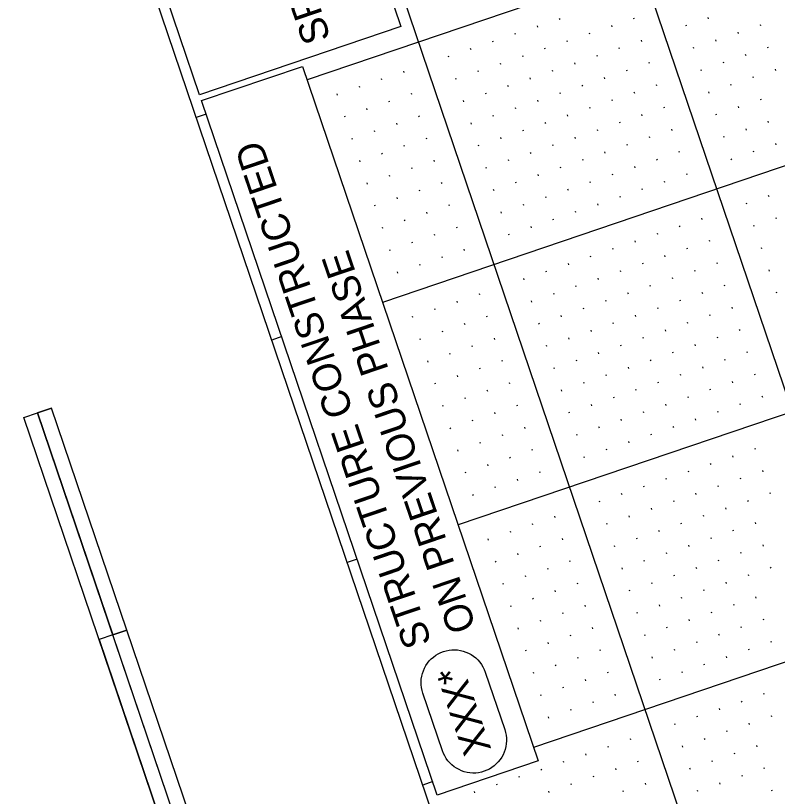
# Model space of a CAD drawing. Extents: x 2150800 to 2152547, y 141860 to 143950.
# Drawn here: x 2151773.3 to 2151935.4, y 142302.8 to 142468.9 of the extents above; entities that cross this region are included whole.
import ezdxf

# ---------------------------------------------------------------- set-up
doc = ezdxf.new("R2010")
doc.units = 0
for name, color, linetype in [('PR_Grading_Txt', 7, 'Continuous'), ('PR_Misc_Improvement', 7, 'Continuous'), ('PR_Storm_Txt_PH1B', 7, 'Continuous'), ('SHT_Profile_Grid_Major', 7, 'Continuous'), ('SHT_Profile_Grid_Minor', 7, 'Continuous'), ('SHT_Scale', 7, 'Continuous'), ('SHT_Sheet_Border', 7, 'Continuous')]:
    doc.layers.add(name, color=color, linetype=linetype)

msp = doc.modelspace()

# ---------------------------------------------------------------- linework, layer by layer
at = {"layer": 'PR_Misc_Improvement'}
for points in [[(2151812.44, 142452.11), (2151783.11, 142538.56), (2151825.94, 142553.09), (2151855.27, 142466.63)], [(2151863, 142303.07), (2151812.86, 142450.86), (2151834.34, 142458.14), (2151884.47, 142310.35)]]:
    msp.add_lwpolyline(points, close=True, dxfattribs=at)
at = {"layer": 'PR_Storm_Txt_PH1B'}
for points in [[(2151859.94, 142324.75), (2151859.77, 142325.34), (2151859.65, 142325.94), (2151859.59, 142326.54), (2151859.57, 142327.15), (2151859.61, 142327.76), (2151859.71, 142328.37), (2151859.85, 142328.96), (2151860.05, 142329.54), (2151860.29, 142330.1), (2151860.59, 142330.63), (2151860.93, 142331.14), (2151861.31, 142331.62), (2151861.73, 142332.06), (2151862.19, 142332.46), (2151862.68, 142332.82), (2151863.21, 142333.14), (2151863.75, 142333.41), (2151864.32, 142333.63), (2151864.32, 142333.63), (2151864.91, 142333.8), (2151865.51, 142333.92), (2151866.12, 142333.99), (2151866.73, 142334), (2151867.34, 142333.96), (2151867.94, 142333.87), (2151868.53, 142333.72), (2151869.11, 142333.52), (2151869.67, 142333.28), (2151870.2, 142332.98), (2151870.71, 142332.64), (2151871.19, 142332.26), (2151871.63, 142331.84), (2151872.03, 142331.38), (2151872.39, 142330.89), (2151872.71, 142330.37), (2151872.98, 142329.82), (2151873.2, 142329.25)], [(2151873.2, 142329.25), (2151877.35, 142317.01)], [(2151864.09, 142312.52), (2151859.94, 142324.75)], [(2151877.35, 142317.01), (2151877.52, 142316.43), (2151877.64, 142315.83), (2151877.71, 142315.22), (2151877.72, 142314.61), (2151877.68, 142314), (2151877.59, 142313.4), (2151877.44, 142312.8), (2151877.25, 142312.23), (2151877, 142311.67), (2151876.71, 142311.13), (2151876.37, 142310.62), (2151875.98, 142310.15), (2151875.56, 142309.71), (2151875.1, 142309.3), (2151874.61, 142308.94), (2151874.09, 142308.63), (2151873.54, 142308.36), (2151872.97, 142308.14), (2151872.97, 142308.14), (2151872.39, 142307.96), (2151871.79, 142307.85), (2151871.18, 142307.78), (2151870.57, 142307.77), (2151869.96, 142307.81), (2151869.36, 142307.9), (2151868.76, 142308.04), (2151868.18, 142308.24), (2151867.63, 142308.49), (2151867.09, 142308.78), (2151866.58, 142309.12), (2151866.11, 142309.5), (2151865.67, 142309.92), (2151865.26, 142310.38), (2151864.9, 142310.88), (2151864.59, 142311.4), (2151864.32, 142311.95), (2151864.09, 142312.52)]]:
    msp.add_lwpolyline(points, dxfattribs=at)
at = {"layer": 'SHT_Profile_Grid_Major'}
for p, q in [((2151982.71, 142254.48), (2151476.72, 143745.99)), ((2151935.36, 142238.42), (2151429.37, 143729.93)), ((2152285.21, 142607.9), (2151835.31, 142455.27)), ((2152301.27, 142560.55), (2151851.37, 142407.92)), ((2152317.33, 142513.2), (2151867.44, 142360.57)), ((2152333.4, 142465.85), (2151883.5, 142313.22)), ((2151813.84, 142447.99), (2151811.71, 142447.26)), ((2151829.9, 142400.64), (2151827.78, 142399.91)), ((2151845.97, 142353.29), (2151843.84, 142352.56)), ((2151862.03, 142305.94), (2151859.9, 142305.22))]:
    msp.add_line(p, q, dxfattribs=at)
at = {"layer": 'SHT_Profile_Grid_Minor'}
for p, q in [((2151920.74, 142468.28), (2151920.66, 142468.52)), ((2151889.12, 142468.11), (2151889.04, 142468.35)), ((2151900.2, 142466.59), (2151900.12, 142466.83)), ((2151904.93, 142468.2), (2151904.85, 142468.43)), ((2151916.01, 142466.67), (2151915.93, 142466.91)), ((2151931.82, 142466.76), (2151931.74, 142466.99)), ((2151879.65, 142464.9), (2151879.57, 142465.14)), ((2151884.38, 142466.51), (2151884.3, 142466.74)), ((2151895.46, 142464.98), (2151895.38, 142465.22)), ((2151927.08, 142465.15), (2151927, 142465.39)), ((2151874.91, 142463.29), (2151874.83, 142463.53)), ((2151890.73, 142463.38), (2151890.65, 142463.61)), ((2151906.54, 142463.46), (2151906.46, 142463.7)), ((2151922.35, 142463.54), (2151922.27, 142463.78)), ((2151870.18, 142461.69), (2151870.1, 142461.92)), ((2151885.99, 142461.77), (2151885.91, 142462.01)), ((2151901.8, 142461.85), (2151901.72, 142462.09)), ((2151917.61, 142461.94), (2151917.53, 142462.18)), ((2151933.42, 142462.02), (2151933.34, 142462.26)), ((2151865.44, 142460.08), (2151865.36, 142460.32)), ((2151881.26, 142460.16), (2151881.18, 142460.4)), ((2151897.07, 142460.25), (2151896.99, 142460.48)), ((2151928.69, 142460.42), (2151928.61, 142460.65)), ((2151876.52, 142458.56), (2151876.44, 142458.79)), ((2151892.33, 142458.64), (2151892.25, 142458.88)), ((2151908.14, 142458.73), (2151908.06, 142458.96)), ((2151923.95, 142458.81), (2151923.87, 142459.05)), ((2151855.97, 142456.87), (2151855.89, 142457.1)), ((2151871.79, 142456.95), (2151871.71, 142457.19)), ((2151887.6, 142457.04), (2151887.52, 142457.27)), ((2151903.41, 142457.12), (2151903.33, 142457.36)), ((2151919.22, 142457.2), (2151919.14, 142457.44)), ((2151935.03, 142457.29), (2151934.95, 142457.52)), ((2151851.24, 142455.26), (2151851.16, 142455.5)), ((2151867.05, 142455.35), (2151866.97, 142455.58)), ((2151882.86, 142455.43), (2151882.78, 142455.67)), ((2151898.67, 142455.51), (2151898.59, 142455.75)), ((2151930.3, 142455.68), (2151930.22, 142455.92)), ((2151846.5, 142453.65), (2151846.42, 142453.89)), ((2151878.13, 142453.82), (2151878.05, 142454.06)), ((2151893.94, 142453.91), (2151893.86, 142454.14)), ((2151909.75, 142453.99), (2151909.67, 142454.23)), ((2151925.56, 142454.07), (2151925.48, 142454.31)), ((2151841.77, 142452.05), (2151841.69, 142452.29)), ((2151857.58, 142452.13), (2151857.5, 142452.37)), ((2151873.39, 142452.22), (2151873.31, 142452.45)), ((2151889.2, 142452.3), (2151889.12, 142452.54)), ((2151905.01, 142452.38), (2151904.93, 142452.62)), ((2151920.83, 142452.47), (2151920.75, 142452.71)), ((2151852.85, 142450.53), (2151852.77, 142450.76)), ((2151868.66, 142450.61), (2151868.58, 142450.85)), ((2151884.47, 142450.69), (2151884.39, 142450.93)), ((2151900.28, 142450.78), (2151900.2, 142451.01)), ((2151931.9, 142450.95), (2151931.82, 142451.18)), ((2151848.11, 142448.92), (2151848.03, 142449.16)), ((2151879.73, 142449.09), (2151879.65, 142449.32)), ((2151895.54, 142449.17), (2151895.46, 142449.41)), ((2151911.36, 142449.26), (2151911.28, 142449.49)), ((2151927.17, 142449.34), (2151927.09, 142449.58)), ((2151843.38, 142447.31), (2151843.3, 142447.55)), ((2151859.19, 142447.4), (2151859.11, 142447.63)), ((2151875, 142447.48), (2151874.92, 142447.72)), ((2151890.81, 142447.57), (2151890.73, 142447.8)), ((2151906.62, 142447.65), (2151906.54, 142447.89)), ((2151922.43, 142447.73), (2151922.35, 142447.97)), ((2151854.45, 142445.79), (2151854.37, 142446.03)), ((2151870.26, 142445.88), (2151870.18, 142446.11)), ((2151886.07, 142445.96), (2151885.99, 142446.2)), ((2151901.89, 142446.04), (2151901.81, 142446.28)), ((2151933.51, 142446.21), (2151933.43, 142446.45)), ((2151849.72, 142444.18), (2151849.64, 142444.42)), ((2151881.34, 142444.35), (2151881.26, 142444.59)), ((2151897.15, 142444.44), (2151897.07, 142444.67)), ((2151912.96, 142444.52), (2151912.88, 142444.76)), ((2151928.77, 142444.6), (2151928.69, 142444.84)), ((2151844.98, 142442.58), (2151844.9, 142442.82)), ((2151860.79, 142442.66), (2151860.71, 142442.9)), ((2151876.6, 142442.75), (2151876.52, 142442.98)), ((2151892.42, 142442.83), (2151892.34, 142443.07)), ((2151908.23, 142442.91), (2151908.15, 142443.15)), ((2151924.04, 142443), (2151923.96, 142443.24)), ((2151856.06, 142441.06), (2151855.98, 142441.29)), ((2151871.87, 142441.14), (2151871.79, 142441.38)), ((2151887.68, 142441.22), (2151887.6, 142441.46)), ((2151903.49, 142441.31), (2151903.41, 142441.55)), ((2151935.11, 142441.48), (2151935.03, 142441.71)), ((2151851.32, 142439.45), (2151851.24, 142439.69)), ((2151882.95, 142439.62), (2151882.87, 142439.85)), ((2151898.76, 142439.7), (2151898.68, 142439.94)), ((2151914.57, 142439.79), (2151914.49, 142440.02)), ((2151930.38, 142439.87), (2151930.3, 142440.11)), ((2151846.59, 142437.84), (2151846.51, 142438.08)), ((2151862.4, 142437.93), (2151862.32, 142438.16)), ((2151878.21, 142438.01), (2151878.13, 142438.25)), ((2151894.02, 142438.1), (2151893.94, 142438.33)), ((2151909.83, 142438.18), (2151909.75, 142438.42)), ((2151925.64, 142438.26), (2151925.56, 142438.5)), ((2151857.66, 142436.32), (2151857.58, 142436.56)), ((2151873.48, 142436.41), (2151873.4, 142436.64)), ((2151889.29, 142436.49), (2151889.21, 142436.73)), ((2151905.1, 142436.57), (2151905.02, 142436.81)), ((2151916.17, 142435.05), (2151916.09, 142435.29)), ((2151852.93, 142434.72), (2151852.85, 142434.95)), ((2151884.55, 142434.88), (2151884.47, 142435.12)), ((2151895.63, 142433.36), (2151895.55, 142433.6)), ((2151900.36, 142434.97), (2151900.28, 142435.2)), ((2151911.44, 142433.44), (2151911.36, 142433.68)), ((2151848.19, 142433.11), (2151848.11, 142433.35)), ((2151864.01, 142433.19), (2151863.93, 142433.43)), ((2151875.08, 142431.67), (2151875, 142431.91)), ((2151879.82, 142433.28), (2151879.74, 142433.51)), ((2151890.89, 142431.75), (2151890.81, 142431.99)), ((2151906.7, 142431.84), (2151906.62, 142432.08)), ((2151859.27, 142431.59), (2151859.19, 142431.82)), ((2151886.16, 142430.15), (2151886.08, 142430.38)), ((2151901.97, 142430.23), (2151901.89, 142430.47)), ((2151933.59, 142430.4), (2151933.51, 142430.64)), ((2151849.8, 142428.37), (2151849.72, 142428.61)), ((2151854.54, 142429.98), (2151854.46, 142430.22)), ((2151865.61, 142428.46), (2151865.53, 142428.69)), ((2151881.42, 142428.54), (2151881.34, 142428.78)), ((2151897.23, 142428.63), (2151897.15, 142428.86)), ((2151928.86, 142428.79), (2151928.78, 142429.03)), ((2151860.88, 142426.85), (2151860.8, 142427.09)), ((2151876.69, 142426.94), (2151876.61, 142427.17)), ((2151892.5, 142427.02), (2151892.42, 142427.26)), ((2151856.14, 142425.25), (2151856.06, 142425.48)), ((2151887.76, 142425.41), (2151887.68, 142425.65)), ((2151919.39, 142425.58), (2151919.31, 142425.82)), ((2151935.2, 142425.67), (2151935.12, 142425.9)), ((2151851.41, 142423.64), (2151851.33, 142423.88)), ((2151867.22, 142423.72), (2151867.14, 142423.96)), ((2151883.03, 142423.81), (2151882.95, 142424.04)), ((2151914.65, 142423.97), (2151914.57, 142424.21)), ((2151930.46, 142424.06), (2151930.38, 142424.3)), ((2151862.48, 142422.12), (2151862.4, 142422.35)), ((2151878.3, 142422.2), (2151878.21, 142422.44)), ((2151909.92, 142422.37), (2151909.84, 142422.61)), ((2151857.75, 142420.51), (2151857.67, 142420.75)), ((2151905.18, 142420.76), (2151905.1, 142421)), ((2151920.99, 142420.85), (2151920.91, 142421.08)), ((2151853.01, 142418.9), (2151852.93, 142419.14)), ((2151868.83, 142418.99), (2151868.74, 142419.22)), ((2151900.45, 142419.16), (2151900.37, 142419.39)), ((2151916.26, 142419.24), (2151916.18, 142419.48)), ((2151932.07, 142419.32), (2151931.99, 142419.56)), ((2151864.09, 142417.38), (2151864.01, 142417.62)), ((2151895.71, 142417.55), (2151895.63, 142417.79)), ((2151911.52, 142417.63), (2151911.44, 142417.87)), ((2151859.36, 142415.78), (2151859.27, 142416.01)), ((2151890.98, 142415.94), (2151890.9, 142416.18)), ((2151906.79, 142416.03), (2151906.71, 142416.26)), ((2151922.6, 142416.11), (2151922.52, 142416.35)), ((2151854.62, 142414.17), (2151854.54, 142414.41)), ((2151886.24, 142414.34), (2151886.16, 142414.57)), ((2151902.05, 142414.42), (2151901.97, 142414.66)), ((2151917.86, 142414.5), (2151917.78, 142414.74)), ((2151933.68, 142414.59), (2151933.6, 142414.83)), ((2151881.51, 142412.73), (2151881.43, 142412.97)), ((2151897.32, 142412.81), (2151897.24, 142413.05)), ((2151913.13, 142412.9), (2151913.05, 142413.14)), ((2151892.58, 142411.21), (2151892.5, 142411.45)), ((2151908.4, 142411.29), (2151908.31, 142411.53)), ((2151924.21, 142411.38), (2151924.13, 142411.61)), ((2151872.04, 142409.52), (2151871.96, 142409.75)), ((2151887.85, 142409.6), (2151887.77, 142409.84)), ((2151903.66, 142409.69), (2151903.58, 142409.92)), ((2151919.47, 142409.77), (2151919.39, 142410.01)), ((2151935.28, 142409.85), (2151935.2, 142410.09)), ((2151867.3, 142407.91), (2151867.22, 142408.15)), ((2151883.11, 142408), (2151883.03, 142408.23)), ((2151898.93, 142408.08), (2151898.84, 142408.32)), ((2151914.74, 142408.16), (2151914.66, 142408.4)), ((2151862.57, 142406.31), (2151862.49, 142406.54)), ((2151894.19, 142406.47), (2151894.11, 142406.71)), ((2151910, 142406.56), (2151909.92, 142406.79)), ((2151925.81, 142406.64), (2151925.73, 142406.88)), ((2151857.83, 142404.7), (2151857.75, 142404.94)), ((2151873.64, 142404.78), (2151873.56, 142405.02)), ((2151889.46, 142404.87), (2151889.37, 142405.1)), ((2151905.27, 142404.95), (2151905.19, 142405.19)), ((2151916.34, 142403.43), (2151916.26, 142403.67)), ((2151921.08, 142405.04), (2151921, 142405.27)), ((2151868.91, 142403.18), (2151868.83, 142403.41)), ((2151884.72, 142403.26), (2151884.64, 142403.5)), ((2151900.53, 142403.34), (2151900.45, 142403.58)), ((2151911.61, 142401.82), (2151911.53, 142402.06)), ((2151927.42, 142401.91), (2151927.34, 142402.14)), ((2151864.17, 142401.57), (2151864.09, 142401.81)), ((2151891.06, 142400.13), (2151890.98, 142400.37)), ((2151895.8, 142401.74), (2151895.72, 142401.98)), ((2151906.87, 142400.22), (2151906.79, 142400.45)), ((2151922.68, 142400.3), (2151922.6, 142400.54)), ((2151859.44, 142399.96), (2151859.36, 142400.2)), ((2151870.52, 142398.44), (2151870.44, 142398.68)), ((2151875.25, 142400.05), (2151875.17, 142400.28)), ((2151886.33, 142398.53), (2151886.25, 142398.76)), ((2151902.14, 142398.61), (2151902.06, 142398.85)), ((2151917.95, 142398.69), (2151917.87, 142398.93)), ((2151865.78, 142396.84), (2151865.7, 142397.07)), ((2151897.4, 142397), (2151897.32, 142397.24)), ((2151913.21, 142397.09), (2151913.13, 142397.32)), ((2151929.03, 142397.17), (2151928.94, 142397.41)), ((2151861.05, 142395.23), (2151860.97, 142395.47)), ((2151876.86, 142395.31), (2151876.78, 142395.55)), ((2151892.67, 142395.4), (2151892.59, 142395.63)), ((2151908.48, 142395.48), (2151908.4, 142395.72)), ((2151924.29, 142395.57), (2151924.21, 142395.8)), ((2151872.12, 142393.71), (2151872.04, 142393.94)), ((2151887.93, 142393.79), (2151887.85, 142394.03)), ((2151903.74, 142393.87), (2151903.66, 142394.11)), ((2151919.56, 142393.96), (2151919.47, 142394.2)), ((2151867.39, 142392.1), (2151867.31, 142392.34)), ((2151899.01, 142392.27), (2151898.93, 142392.51)), ((2151914.82, 142392.35), (2151914.74, 142392.59)), ((2151930.63, 142392.44), (2151930.55, 142392.67)), ((2151862.65, 142390.49), (2151862.57, 142390.73)), ((2151878.46, 142390.58), (2151878.38, 142390.81)), ((2151894.27, 142390.66), (2151894.19, 142390.9)), ((2151910.09, 142390.75), (2151910.01, 142390.98)), ((2151925.9, 142390.83), (2151925.82, 142391.07)), ((2151873.73, 142388.97), (2151873.65, 142389.21)), ((2151889.54, 142389.06), (2151889.46, 142389.29)), ((2151905.35, 142389.14), (2151905.27, 142389.38)), ((2151921.16, 142389.22), (2151921.08, 142389.46)), ((2151868.99, 142387.37), (2151868.91, 142387.6)), ((2151900.62, 142387.53), (2151900.54, 142387.77)), ((2151916.43, 142387.62), (2151916.35, 142387.85)), ((2151932.24, 142387.7), (2151932.16, 142387.94)), ((2151864.26, 142385.76), (2151864.18, 142386)), ((2151880.07, 142385.84), (2151879.99, 142386.08)), ((2151895.88, 142385.93), (2151895.8, 142386.16)), ((2151911.69, 142386.01), (2151911.61, 142386.25)), ((2151927.5, 142386.1), (2151927.42, 142386.33)), ((2151875.33, 142384.24), (2151875.25, 142384.47)), ((2151891.15, 142384.32), (2151891.07, 142384.56)), ((2151906.96, 142384.4), (2151906.88, 142384.64)), ((2151922.77, 142384.49), (2151922.69, 142384.73)), ((2151870.6, 142382.63), (2151870.52, 142382.87)), ((2151902.22, 142382.8), (2151902.14, 142383.04)), ((2151918.03, 142382.88), (2151917.95, 142383.12)), ((2151865.86, 142381.02), (2151865.78, 142381.26)), ((2151881.68, 142381.11), (2151881.6, 142381.35)), ((2151897.49, 142381.19), (2151897.41, 142381.43)), ((2151913.3, 142381.28), (2151913.22, 142381.51)), ((2151876.94, 142379.5), (2151876.86, 142379.74)), ((2151892.75, 142379.59), (2151892.67, 142379.82)), ((2151908.56, 142379.67), (2151908.48, 142379.91)), ((2151872.21, 142377.9), (2151872.13, 142378.13)), ((2151903.83, 142378.06), (2151903.75, 142378.3)), ((2151867.47, 142376.29), (2151867.39, 142376.53)), ((2151883.28, 142376.37), (2151883.2, 142376.61)), ((2151899.09, 142376.46), (2151899.01, 142376.69)), ((2151930.72, 142376.63), (2151930.64, 142376.86)), ((2151878.55, 142374.77), (2151878.47, 142375)), ((2151894.36, 142374.85), (2151894.28, 142375.09)), ((2151925.98, 142375.02), (2151925.9, 142375.26)), ((2151873.81, 142373.16), (2151873.73, 142373.4)), ((2151921.25, 142373.41), (2151921.17, 142373.65)), ((2151932.32, 142371.89), (2151932.24, 142372.13)), ((2151869.08, 142371.55), (2151869, 142371.79)), ((2151884.89, 142371.64), (2151884.81, 142371.88)), ((2151911.78, 142370.2), (2151911.7, 142370.44)), ((2151916.51, 142371.81), (2151916.43, 142372.04)), ((2151927.59, 142370.28), (2151927.51, 142370.52)), ((2151880.15, 142370.03), (2151880.07, 142370.27)), ((2151907.04, 142368.59), (2151906.96, 142368.83)), ((2151922.85, 142368.68), (2151922.77, 142368.91)), ((2151875.42, 142368.43), (2151875.34, 142368.66)), ((2151902.31, 142366.99), (2151902.23, 142367.22)), ((2151918.12, 142367.07), (2151918.04, 142367.31)), ((2151933.93, 142367.16), (2151933.85, 142367.39)), ((2151870.68, 142366.82), (2151870.6, 142367.06)), ((2151897.57, 142365.38), (2151897.49, 142365.62)), ((2151913.38, 142365.47), (2151913.3, 142365.7)), ((2151929.19, 142365.55), (2151929.11, 142365.79)), ((2151908.65, 142363.86), (2151908.57, 142364.1)), ((2151924.46, 142363.94), (2151924.38, 142364.18)), ((2151888.1, 142362.17), (2151888.02, 142362.41)), ((2151903.91, 142362.25), (2151903.83, 142362.49)), ((2151919.72, 142362.34), (2151919.64, 142362.57)), ((2151883.37, 142360.56), (2151883.29, 142360.8)), ((2151899.18, 142360.65), (2151899.1, 142360.88)), ((2151914.99, 142360.73), (2151914.91, 142360.97)), ((2151930.8, 142360.81), (2151930.72, 142361.05)), ((2151878.63, 142358.96), (2151878.55, 142359.19)), ((2151910.25, 142359.12), (2151910.17, 142359.36)), ((2151926.06, 142359.21), (2151925.98, 142359.44)), ((2151873.9, 142357.35), (2151873.82, 142357.59)), ((2151889.71, 142357.43), (2151889.63, 142357.67)), ((2151905.52, 142357.52), (2151905.44, 142357.75)), ((2151921.33, 142357.6), (2151921.25, 142357.84)), ((2151884.97, 142355.83), (2151884.89, 142356.06)), ((2151900.78, 142355.91), (2151900.7, 142356.15)), ((2151916.59, 142356), (2151916.51, 142356.23)), ((2151932.41, 142356.08), (2151932.33, 142356.32)), ((2151880.24, 142354.22), (2151880.16, 142354.46)), ((2151911.86, 142354.39), (2151911.78, 142354.63)), ((2151927.67, 142354.47), (2151927.59, 142354.71)), ((2151875.5, 142352.61), (2151875.42, 142352.85)), ((2151891.31, 142352.7), (2151891.23, 142352.94)), ((2151907.12, 142352.78), (2151907.04, 142353.02)), ((2151922.94, 142352.87), (2151922.86, 142353.1)), ((2151886.58, 142351.09), (2151886.5, 142351.33)), ((2151902.39, 142351.18), (2151902.31, 142351.41)), ((2151918.2, 142351.26), (2151918.12, 142351.5)), ((2151934.01, 142351.34), (2151933.93, 142351.58)), ((2151881.84, 142349.49), (2151881.76, 142349.72)), ((2151913.47, 142349.65), (2151913.39, 142349.89)), ((2151929.28, 142349.74), (2151929.2, 142349.97)), ((2151877.11, 142347.88), (2151877.03, 142348.12)), ((2151892.92, 142347.96), (2151892.84, 142348.2)), ((2151908.73, 142348.05), (2151908.65, 142348.28)), ((2151924.54, 142348.13), (2151924.46, 142348.37)), ((2151888.18, 142346.36), (2151888.1, 142346.59)), ((2151904, 142346.44), (2151903.92, 142346.68)), ((2151919.81, 142346.53), (2151919.73, 142346.76)), ((2151883.45, 142344.75), (2151883.37, 142344.99)), ((2151915.07, 142344.92), (2151914.99, 142345.16)), ((2151930.88, 142345), (2151930.8, 142345.24)), ((2151878.72, 142343.14), (2151878.63, 142343.38)), ((2151894.53, 142343.23), (2151894.45, 142343.47)), ((2151910.34, 142343.31), (2151910.26, 142343.55)), ((2151926.15, 142343.4), (2151926.07, 142343.63)), ((2151889.79, 142341.62), (2151889.71, 142341.86)), ((2151905.6, 142341.71), (2151905.52, 142341.94)), ((2151921.41, 142341.79), (2151921.33, 142342.03)), ((2151885.06, 142340.02), (2151884.98, 142340.25)), ((2151916.68, 142340.18), (2151916.6, 142340.42)), ((2151927.75, 142338.66), (2151927.67, 142338.9)), ((2151932.49, 142340.27), (2151932.41, 142340.5)), ((2151880.32, 142338.41), (2151880.24, 142338.65)), ((2151896.13, 142338.49), (2151896.05, 142338.73)), ((2151907.21, 142336.97), (2151907.13, 142337.21)), ((2151911.94, 142338.58), (2151911.86, 142338.81)), ((2151923.02, 142337.06), (2151922.94, 142337.29)), ((2151891.4, 142336.89), (2151891.32, 142337.12)), ((2151918.28, 142335.45), (2151918.2, 142335.69)), ((2151934.1, 142335.53), (2151934.02, 142335.77)), ((2151881.93, 142333.67), (2151881.85, 142333.91)), ((2151886.66, 142335.28), (2151886.58, 142335.52)), ((2151897.74, 142333.76), (2151897.66, 142334)), ((2151913.55, 142333.84), (2151913.47, 142334.08)), ((2151929.36, 142333.93), (2151929.28, 142334.16)), ((2151893, 142332.15), (2151892.92, 142332.39)), ((2151908.82, 142332.24), (2151908.73, 142332.47)), ((2151924.63, 142332.32), (2151924.55, 142332.56)), ((2151888.27, 142330.55), (2151888.19, 142330.78)), ((2151919.89, 142330.71), (2151919.81, 142330.95)), ((2151883.53, 142328.94), (2151883.45, 142329.18)), ((2151899.35, 142329.02), (2151899.26, 142329.26)), ((2151915.16, 142329.11), (2151915.08, 142329.34)), ((2151894.61, 142327.42), (2151894.53, 142327.65)), ((2151910.42, 142327.5), (2151910.34, 142327.74)), ((2151889.88, 142325.81), (2151889.79, 142326.05)), ((2151885.14, 142324.2), (2151885.06, 142324.44)), ((2151900.95, 142324.29), (2151900.87, 142324.53)), ((2151932.57, 142324.46), (2151932.49, 142324.69)), ((2151896.22, 142322.68), (2151896.14, 142322.92)), ((2151927.84, 142322.85), (2151927.76, 142323.09)), ((2151891.48, 142321.08), (2151891.4, 142321.31)), ((2151923.1, 142321.24), (2151923.02, 142321.48)), ((2151886.75, 142319.47), (2151886.67, 142319.71)), ((2151918.37, 142319.64), (2151918.29, 142319.87)), ((2151934.18, 142319.72), (2151934.1, 142319.96)), ((2151913.63, 142318.03), (2151913.55, 142318.27)), ((2151929.45, 142318.12), (2151929.36, 142318.35)), ((2151924.71, 142316.51), (2151924.63, 142316.75)), ((2151904.16, 142314.82), (2151904.08, 142315.06)), ((2151919.98, 142314.9), (2151919.89, 142315.14)), ((2151899.43, 142313.21), (2151899.35, 142313.45)), ((2151915.24, 142313.3), (2151915.16, 142313.53)), ((2151931.05, 142313.38), (2151930.97, 142313.62)), ((2151894.69, 142311.61), (2151894.61, 142311.84)), ((2151926.32, 142311.77), (2151926.24, 142312.01)), ((2151889.96, 142310), (2151889.88, 142310.24)), ((2151905.77, 142310.08), (2151905.69, 142310.32)), ((2151921.58, 142310.17), (2151921.5, 142310.4)), ((2151885.22, 142308.39), (2151885.14, 142308.63)), ((2151901.04, 142308.48), (2151900.96, 142308.71)), ((2151916.85, 142308.56), (2151916.77, 142308.8)), ((2151932.66, 142308.65), (2151932.58, 142308.88)), ((2151880.49, 142306.79), (2151880.41, 142307.02)), ((2151896.3, 142306.87), (2151896.22, 142307.11)), ((2151923.19, 142305.43), (2151923.11, 142305.67)), ((2151927.92, 142307.04), (2151927.84, 142307.28)), ((2151875.75, 142305.18), (2151875.67, 142305.42)), ((2151891.57, 142305.27), (2151891.49, 142305.5)), ((2151902.64, 142303.74), (2151902.56, 142303.98)), ((2151907.38, 142305.35), (2151907.3, 142305.59)), ((2151918.45, 142303.83), (2151918.37, 142304.06)), ((2151934.26, 142303.91), (2151934.18, 142304.15)), ((2151871.02, 142303.57), (2151870.94, 142303.81)), ((2151886.83, 142303.66), (2151886.75, 142303.9))]:
    msp.add_line(p, q, dxfattribs=at)
at = {"layer": 'SHT_Scale'}
for p, q in [((2151777.97, 142384.42), (2151780.93, 142385.42)), ((2151780.93, 142385.42), (2151777.97, 142384.42)), ((2151829, 142243.72), (2151780.93, 142385.42)), ((2151796.95, 142338.19), (2151780.93, 142385.42)), ((2151775.01, 142383.41), (2151777.97, 142384.42)), ((2151810.02, 142289.95), (2151777.97, 142384.42)), ((2151777.97, 142384.42), (2151793.99, 142337.18)), ((2151823.08, 142241.71), (2151775.01, 142383.41)), ((2151796.95, 142338.19), (2151793.99, 142337.18)), ((2151793.99, 142337.18), (2151796.95, 142338.19)), ((2151793.99, 142337.18), (2151791.03, 142336.18)), ((2151793.99, 142337.18), (2151791.03, 142336.18)), ((2151791.03, 142336.18), (2151807.06, 142288.95)), ((2151810.02, 142289.95), (2151793.99, 142337.18))]:
    msp.add_line(p, q, dxfattribs=at)
at = {"layer": 'SHT_Sheet_Border'}
msp.add_line((2151888.01, 142222.35), (2151382.02, 143713.86), dxfattribs=at)

# ---------------------------------------------------------------- texts
at = {"layer": 'PR_Grading_Txt'}
for s, p in [('SP. DITCH PAVED', (2151840.39, 142464.13)), ('STRUCTURE CONSTRUCTED', (2151861.84, 142335.54)), ('ON PREVIOUS PHASE', (2151871.33, 142338.75))]:
    msp.add_text(s, height=6, rotation=108.7393, dxfattribs=at).set_placement(p)
at = {"layer": 'PR_Storm_Txt_PH1B'}
msp.add_text('XXX*', height=6, rotation=108.7393, dxfattribs=at).set_placement((2151874.54, 142312.84))

doc.saveas('drawing.dxf')
